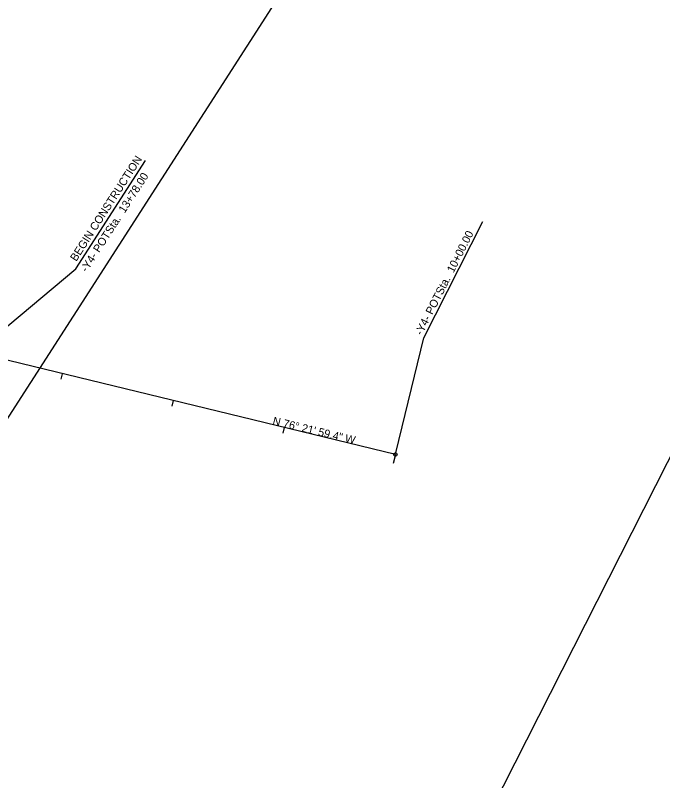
# Model space of a CAD drawing. Extents: x 1974386 to 1979988, y 776712 to 784860.
# Drawn here: x 1977514 to 1978080, y 779824 to 780494 of the extents above; entities that cross this region are included whole.
import ezdxf

# ---------------------------------------------------------------- set-up
doc = ezdxf.new("R2010")
doc.units = 0
for name, color, linetype in [('Default', 7, 'Continuous'), ('Prop Horizontal Alignment', 7, 'Continuous'), ('Prop Horizontal Alignment Direction Label', 7, 'Continuous'), ('Prop Horizontal Alignment Station Label', 7, 'Continuous'), ('Prop Horizontal Alignment Tick Large', 7, 'Continuous'), ('Prop Horizontal Alignment Tick Small', 7, 'Continuous'), ('Sheet Layout Plan Border', 7, 'Continuous')]:
    doc.layers.add(name, color=color, linetype=linetype)

msp = doc.modelspace()

# ---------------------------------------------------------------- linework, layer by layer
at = {"layer": 'Default'}
msp.add_lwpolyline([(1978009.96, 784859.92), (1974385.88, 777715.09), (1976364.02, 776711.71), (1979988.11, 783856.54)], close=True, dxfattribs=at)
at = {"layer": 'Prop Horizontal Alignment'}
for p, q in [((1977701.03, 780144.83), (1977115.39, 780286.87)), ((1977846.16, 780109.62), (1977701.03, 780144.83))]:
    msp.add_line(p, q, dxfattribs=at)
at = {"layer": 'Prop Horizontal Alignment Station Label'}
for p, q in [((1977566.67, 780272.16), (1977627.54, 780366.81)), ((1977870.96, 780211.87), (1977922.69, 780313.64)), ((1977478.82, 780198.72), (1977566.67, 780272.16)), ((1977846.52, 780111.08), (1977870.96, 780211.87))]:
    msp.add_line(p, q, dxfattribs=at)
msp.add_circle((1977846.16, 780109.62), 1.5, dxfattribs=at)
at = {"layer": 'Prop Horizontal Alignment Tick Large'}
msp.add_line((1977846.16, 780109.62), (1977844.28, 780101.85), dxfattribs=at)
at = {"layer": 'Prop Horizontal Alignment Tick Small'}
for p, q in [((1977554.62, 780180.34), (1977553.44, 780175.48)), ((1977651.8, 780156.76), (1977650.62, 780151.91)), ((1977748.98, 780133.19), (1977747.8, 780128.33))]:
    msp.add_line(p, q, dxfattribs=at)
at = {"layer": 'Sheet Layout Plan Border'}
msp.add_lwpolyline([(1977111.11, 779526.05), (1977868.38, 780703.57), (1976985.24, 781271.52), (1976227.97, 780094)], close=True, dxfattribs=at)

# ---------------------------------------------------------------- texts
at = {"layer": 'Prop Horizontal Alignment Direction Label'}
msp.add_text('N 76%%d 21\' 59.4" W', height=7, rotation=346.36649, dxfattribs=at).set_placement((1977738.3, 780135.99))
at = {"layer": 'Prop Horizontal Alignment Station Label'}
for s, rotation, p in [('BEGIN CONSTRUCTION', 57.25495, (1977566.91, 780278.07)), ('-Y4- POTSta.  13+78.00', 57.25495, (1977576.07, 780268.69)), ('-Y4- POTSta.  10+00.00', 63.1044, (1977869.24, 780213.37))]:
    msp.add_text(s, height=7, rotation=rotation, dxfattribs=at).set_placement(p)

doc.saveas('drawing.dxf')
